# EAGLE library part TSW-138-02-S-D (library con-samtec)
THROUGH-HOLE .025" SQ POST HEADER Source: Samtec TSW.pdf
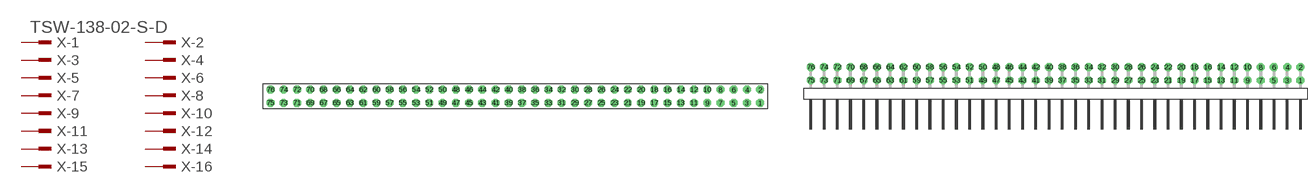
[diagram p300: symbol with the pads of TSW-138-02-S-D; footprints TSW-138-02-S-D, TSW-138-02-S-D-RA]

Designator prefix X; gates -1=MPINV -2=MPIN -3=MPIN -4=MPIN -5=MPIN -6=MPIN -7=MPIN -8=MPIN -9=MPIN -10=MPIN -11=MPIN -12=MPIN -13=MPIN -14=MPIN -15=MPIN -16=MPIN -17=MPIN -18=MPIN -19=MPIN -20=MPIN -21=MPIN -22=MPIN -23=MPIN -24=MPIN -25=MPIN -26=MPIN -27=MPIN -28=MPIN -29=MPIN -30=MPIN -31=MPIN -32=MPIN -33=MPIN -34=MPIN -35=MPIN -36=MPIN -37=MPIN -38=MPIN -39=MPIN -40=MPIN -41=MPIN -42=MPIN -43=MPIN -44=MPIN -45=MPIN -46=MPIN -47=MPIN -48=MPIN -49=MPIN -50=MPIN -51=MPIN -52=MPIN -53=MPIN -54=MPIN -55=MPIN -56=MPIN -57=MPIN -58=MPIN -59=MPIN -60=MPIN -61=MPIN -62=MPIN -63=MPIN -64=MPIN -65=MPIN -66=MPIN -67=MPIN -68=MPIN -69=MPIN -70=MPIN -71=MPIN -72=MPIN -73=MPIN -74=MPIN -75=MPIN -76=MPIN

## TSW-138-02-S-D (OC_FARNELL: unknown; OC_NEWARK: unknown)  [TSW-138-02-S-D]
1  -1:1  pas
2  -2:1  pas
3  -3:1  pas
4  -4:1  pas
5  -5:1  pas
6  -6:1  pas
7  -7:1  pas
8  -8:1  pas
9  -9:1  pas
10  -10:1  pas
11  -11:1  pas
12  -12:1  pas
13  -13:1  pas
14  -14:1  pas
15  -15:1  pas
16  -16:1  pas
17  -17:1  pas
18  -18:1  pas
19  -19:1  pas
20  -20:1  pas
21  -21:1  pas
22  -22:1  pas
23  -23:1  pas
24  -24:1  pas
25  -25:1  pas
26  -26:1  pas
27  -27:1  pas
28  -28:1  pas
29  -29:1  pas
30  -30:1  pas
31  -31:1  pas
32  -32:1  pas
33  -33:1  pas
34  -34:1  pas
35  -35:1  pas
36  -36:1  pas
37  -37:1  pas
38  -38:1  pas
39  -39:1  pas
40  -40:1  pas
41  -41:1  pas
42  -42:1  pas
43  -43:1  pas
44  -44:1  pas
45  -45:1  pas
46  -46:1  pas
47  -47:1  pas
48  -48:1  pas
49  -49:1  pas
50  -50:1  pas
51  -51:1  pas
52  -52:1  pas
53  -53:1  pas
54  -54:1  pas
55  -55:1  pas
56  -56:1  pas
57  -57:1  pas
58  -58:1  pas
59  -59:1  pas
60  -60:1  pas
61  -61:1  pas
62  -62:1  pas
63  -63:1  pas
64  -64:1  pas
65  -65:1  pas
66  -66:1  pas
67  -67:1  pas
68  -68:1  pas
69  -69:1  pas
70  -70:1  pas
71  -71:1  pas
72  -72:1  pas
73  -73:1  pas
74  -74:1  pas
75  -75:1  pas
76  -76:1  pas

## TSW-138-02-S-D-RA (OC_FARNELL: unknown; OC_NEWARK: unknown)  [TSW-138-02-S-D-RA]
Pads as for TSW-138-02-S-D

## Footprint TSW-138-02-S-D (pad centres in mm)
THROUGH-HOLE .025" SQ POST HEADER Source: Samtec TSW.pdf
drill 1 pad 1.5 octagon: 1 46.99,-1.27; 2 46.99,1.27; 3 44.45,-1.27; 4 44.45,1.27; 5 41.91,-1.27; 6 41.91,1.27; 7 39.37,-1.27; 8 39.37,1.27; 9 36.83,-1.27; 10 36.83,1.27; 11 34.29,-1.27; 12 34.29,1.27; 13 31.75,-1.27; 14 31.75,1.27; 15 29.21,-1.27; 16 29.21,1.27; 17 26.67,-1.27; 18 26.67,1.27; 19 24.13,-1.27; 20 24.13,1.27; 21 21.59,-1.27; 22 21.59,1.27; 23 19.05,-1.27; 24 19.05,1.27; 25 16.51,-1.27; 26 16.51,1.27; 27 13.97,-1.27; 28 13.97,1.27; 29 11.43,-1.27; 30 11.43,1.27; 31 8.89,-1.27; 32 8.89,1.27; 33 6.35,-1.27; 34 6.35,1.27; 35 3.81,-1.27; 36 3.81,1.27; 37 1.27,-1.27; 38 1.27,1.27; 39 -1.27,-1.27; 40 -1.27,1.27; 41 -3.81,-1.27; 42 -3.81,1.27; 43 -6.35,-1.27; 44 -6.35,1.27; 45 -8.89,-1.27; 46 -8.89,1.27; 47 -11.43,-1.27; 48 -11.43,1.27; 49 -13.97,-1.27; 50 -13.97,1.27; 51 -16.51,-1.27; 52 -16.51,1.27; 53 -19.05,-1.27; 54 -19.05,1.27; 55 -21.59,-1.27; 56 -21.59,1.27; 57 -24.13,-1.27; 58 -24.13,1.27; 59 -26.67,-1.27; 60 -26.67,1.27; 61 -29.21,-1.27; 62 -29.21,1.27; 63 -31.75,-1.27; 64 -31.75,1.27; 65 -34.29,-1.27; 66 -34.29,1.27; 67 -36.83,-1.27; 68 -36.83,1.27; 69 -39.37,-1.27; 70 -39.37,1.27; 71 -41.91,-1.27; 72 -41.91,1.27; 73 -44.45,-1.27; 74 -44.45,1.27; 75 -46.99,-1.27; 76 -46.99,1.27

## Footprint TSW-138-02-S-D-RA (pad centres in mm)
THROUGH-HOLE .025" SQ POST HEADER Source: Samtec TSW.pdf
drill 1 pad 1.5 octagon: 1 46.99,1.524; 2 46.99,4.064; 3 44.45,1.524; 4 44.45,4.064; 5 41.91,1.524; 6 41.91,4.064; 7 39.37,1.524; 8 39.37,4.064; 9 36.83,1.524; 10 36.83,4.064; 11 34.29,1.524; 12 34.29,4.064; 13 31.75,1.524; 14 31.75,4.064; 15 29.21,1.524; 16 29.21,4.064; 17 26.67,1.524; 18 26.67,4.064; 19 24.13,1.524; 20 24.13,4.064; 21 21.59,1.524; 22 21.59,4.064; 23 19.05,1.524; 24 19.05,4.064; 25 16.51,1.524; 26 16.51,4.064; 27 13.97,1.524; 28 13.97,4.064; 29 11.43,1.524; 30 11.43,4.064; 31 8.89,1.524; 32 8.89,4.064; 33 6.35,1.524; 34 6.35,4.064; 35 3.81,1.524; 36 3.81,4.064; 37 1.27,1.524; 38 1.27,4.064; 39 -1.27,1.524; 40 -1.27,4.064; 41 -3.81,1.524; 42 -3.81,4.064; 43 -6.35,1.524; 44 -6.35,4.064; 45 -8.89,1.524; 46 -8.89,4.064; 47 -11.43,1.524; 48 -11.43,4.064; 49 -13.97,1.524; 50 -13.97,4.064; 51 -16.51,1.524; 52 -16.51,4.064; 53 -19.05,1.524; 54 -19.05,4.064; 55 -21.59,1.524; 56 -21.59,4.064; 57 -24.13,1.524; 58 -24.13,4.064; 59 -26.67,1.524; 60 -26.67,4.064; 61 -29.21,1.524; 62 -29.21,4.064; 63 -31.75,1.524; 64 -31.75,4.064; 65 -34.29,1.524; 66 -34.29,4.064; 67 -36.83,1.524; 68 -36.83,4.064; 69 -39.37,1.524; 70 -39.37,4.064; 71 -41.91,1.524; 72 -41.91,4.064; 73 -44.45,1.524; 74 -44.45,4.064; 75 -46.99,1.524; 76 -46.99,4.064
